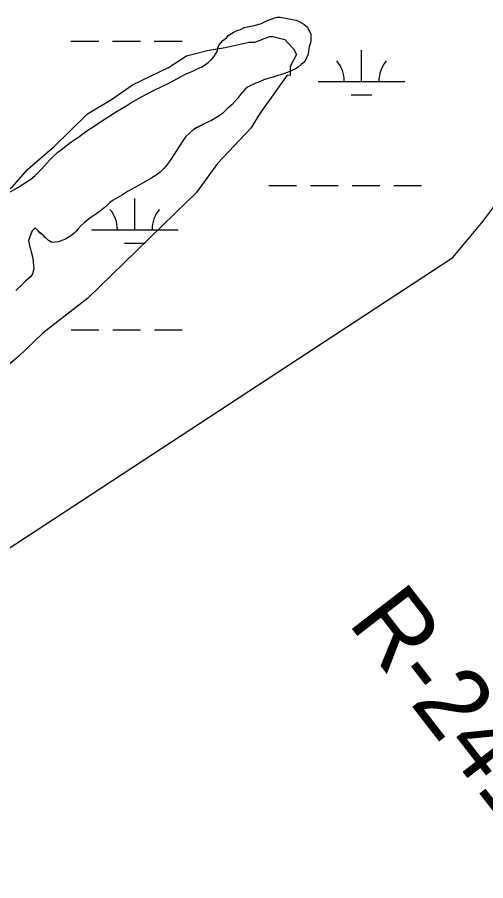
# Model space of a CAD drawing. Extents: x 3279314 to 3317160, y 734079 to 759431.
# Drawn here: x 3303115 to 3303655, y 741916 to 742911 of the extents above; entities that cross this region are included whole.
import ezdxf

# ---------------------------------------------------------------- set-up
doc = ezdxf.new("R2010")
doc.units = 0
for name, color, linetype in [('V-RIVR-RANG-IDEN', 7, 'Continuous'), ('V-SITE-VEGE', 7, 'Continuous'), ('V-TOPO-SHOR', 7, 'Continuous'), ('V-WETL-SWMP', 7, 'Continuous')]:
    doc.layers.add(name, color=color, linetype=linetype)

msp = doc.modelspace()

# ---------------------------------------------------------------- linework, layer by layer
at = {"layer": 'V-SITE-VEGE'}
msp.add_lwpolyline([(3303101.97, 742706.73), (3303116.96, 742715.21), (3303122.8, 742718.8), (3303130.92, 742724.2), (3303136, 742728.29), (3303142.84, 742735.21), (3303146.9, 742739.55), (3303152.47, 742745.95), (3303156.02, 742749.53), (3303162.11, 742755.16), (3303167.69, 742759.27), (3303175.56, 742765.67), (3303178.35, 742767.72), (3303187.74, 742773.88), (3303194.6, 742779.01), (3303205.26, 742785.94), (3303212.37, 742791.07), (3303230.4, 742802.61), (3303241.58, 742809.04), (3303245.13, 742811.35), (3303257.83, 742818.54), (3303273.84, 742827.02), (3303280.7, 742830.11), (3303290.87, 742835.25), (3303309.16, 742845.02), (3303312.97, 742846.82), (3303318.56, 742849.14), (3303322.12, 742850.94), (3303328.22, 742853.52), (3303332.54, 742856.34), (3303335.33, 742858.65), (3303339.39, 742862.23), (3303342.17, 742865.3), (3303345.71, 742871.43), (3303346.46, 742875.26), (3303347.97, 742878.83), (3303352.53, 742883.95), (3303356.59, 742887.02), (3303358.62, 742889.58), (3303362.17, 742892.14), (3303365.47, 742893.94), (3303368.78, 742895.49), (3303372.59, 742896.78), (3303376.91, 742898.84), (3303388.36, 742901.19), (3303397.01, 742903.52), (3303400.31, 742905.32), (3303403.87, 742906.86), (3303412.26, 742909.96), (3303415.32, 742910.74), (3303418.37, 742910.75), (3303426.53, 742909.52), (3303432.65, 742908.27), (3303436.47, 742907.27), (3303439.53, 742906.27), (3303443.11, 742904.5), (3303445.67, 742902.73), (3303450.01, 742899.19), (3303451.81, 742895.12), (3303453.62, 742891.56), (3303453.65, 742883.67), (3303453.16, 742880.1), (3303451.9, 742876.78), (3303450.91, 742871.94), (3303450.67, 742868.37), (3303448.15, 742862.24), (3303445.88, 742858.67), (3303443.08, 742856.62), (3303439.02, 742853.29), (3303436.23, 742851.49), (3303430.39, 742848.66), (3303426.57, 742847.11), (3303421.49, 742845.3), (3303413.35, 742842.97), (3303410.3, 742841.94), (3303404.19, 742840.13), (3303399.61, 742838.58), (3303393.77, 742836), (3303390.21, 742834.97), (3303380.81, 742830.34), (3303378.01, 742827.77), (3303372.69, 742821.89), (3303369.15, 742817.29), (3303363.07, 742810.13), (3303358.25, 742806.03), (3303351.91, 742799.89), (3303346.83, 742796.29), (3303339.22, 742791.68), (3303333.12, 742789.1), (3303321.68, 742783.18), (3303318.12, 742781.13), (3303309.75, 742773.45), (3303306.21, 742768.59), (3303291.55, 742745.6), (3303287.25, 742739.72), (3303284.46, 742736.65), (3303280.15, 742732.3), (3303276.85, 742729.73), (3303270.5, 742725.62), (3303255.01, 742716.89), (3303246.62, 742712.52), (3303242.31, 742709.96), (3303236.72, 742706.11), (3303225.79, 742700.19), (3303222.24, 742697.38), (3303217.17, 742692.51), (3303212.86, 742688.93), (3303205.75, 742683.55), (3303199.66, 742679.69), (3303192.55, 742674.06), (3303189.26, 742670.98), (3303185.71, 742666.89), (3303183.18, 742664.33), (3303180.64, 742661.52), (3303177.34, 742658.95), (3303170.23, 742654.84), (3303162.6, 742652.01), (3303159.04, 742651.73), (3303155.22, 742651.21), (3303151.64, 742653.74), (3303147.8, 742657.03), (3303145.5, 742659.82), (3303141.66, 742662.35), (3303139.36, 742664.63), (3303136.03, 742668.18), (3303132.74, 742664.6), (3303130.22, 742658.98), (3303128.46, 742653.63), (3303129.51, 742647.52), (3303130.8, 742643.7), (3303131.33, 742640.39), (3303133.4, 742633.28), (3303133.67, 742628.94), (3303134.48, 742620.8), (3303132.97, 742615.18), (3303130.95, 742612.12), (3303125.12, 742606.74), (3303120.81, 742602.39), (3303113.96, 742595.99)], dxfattribs=at)
at = {"layer": 'V-TOPO-SHOR'}
for points in [[(3303248.34, 742832.86), (3303289.7, 742852.78), (3303310.43, 742866.16), (3303334.48, 742872.64), (3303355.06, 742875.76), (3303382.54, 742882.19), (3303389.38, 742882.09), (3303406.59, 742888.67), (3303410.01, 742888.62), (3303423.64, 742885), (3303427.01, 742881.53), (3303433.75, 742874.58), (3303437.07, 742867.69), (3303430.02, 742854.1), (3303429.87, 742843.84), (3303426.45, 742843.89), (3303395, 742799.88)], [(3302509.04, 742364.81), (3302602.07, 742407.91), (3302664.17, 742441.2), (3302722.84, 742474.55), (3302798.88, 742524.74), (3302847.23, 742554.82), (3302895.59, 742584.9), (3302964.58, 742621.51), (3303009.46, 742648.22), (3303037.09, 742664.91), (3303075.18, 742695.14), (3303109.7, 742715.16), (3303127.12, 742735.43), (3303158.31, 742762.34), (3303175.68, 742779.2), (3303196.51, 742799.41), (3303224.14, 742816.11), (3303248.34, 742832.86)], [(3303395, 742799.88), (3303384.48, 742782.92), (3303346.23, 742742.43), (3303321.77, 742708.57), (3303297.46, 742684.98), (3303252.32, 742641.17), (3303224.54, 742614.21), (3303196.77, 742587.25), (3303144.83, 742546.95), (3303117.05, 742519.99), (3303068.54, 742479.65), (3303027.13, 742456.32), (3302971.88, 742422.92), (3302927.05, 742399.64), (3302847.79, 742363.18), (3302792.65, 742336.62), (3302706.5, 742296.84), (3302654.82, 742273.66), (3302603.1, 742247.06), (3302520.53, 742217.49)]]:
    msp.add_lwpolyline(points, dxfattribs=at)
at = {"layer": 'V-WETL-SWMP'}
for p, q in [((3303388.36, 742901.19), (3303397.01, 742903.52)), ((3303388.36, 742901.19), (3303397.01, 742903.52)), ((3303397.01, 742903.52), (3303400.31, 742905.32)), ((3303397.01, 742903.52), (3303400.31, 742905.32)), ((3303400.31, 742905.32), (3303403.87, 742906.86)), ((3303400.31, 742905.32), (3303403.87, 742906.86)), ((3303403.87, 742906.86), (3303412.26, 742909.96)), ((3303403.87, 742906.86), (3303412.26, 742909.96)), ((3303412.26, 742909.96), (3303415.32, 742910.74)), ((3303412.26, 742909.96), (3303415.32, 742910.74)), ((3303415.32, 742910.74), (3303418.37, 742910.75)), ((3303415.32, 742910.74), (3303418.37, 742910.75)), ((3303418.37, 742910.75), (3303426.53, 742909.52)), ((3303418.37, 742910.75), (3303426.53, 742909.52)), ((3303426.53, 742909.52), (3303432.65, 742908.27)), ((3303426.53, 742909.52), (3303432.65, 742908.27)), ((3303432.65, 742908.27), (3303436.47, 742907.27)), ((3303432.65, 742908.27), (3303436.47, 742907.27)), ((3303436.47, 742907.27), (3303439.54, 742906.27)), ((3303436.47, 742907.27), (3303439.54, 742906.27)), ((3303439.54, 742906.27), (3303443.11, 742904.5)), ((3303439.54, 742906.27), (3303443.11, 742904.5)), ((3303443.11, 742904.5), (3303445.67, 742902.73)), ((3303443.11, 742904.5), (3303445.67, 742902.73)), ((3303445.67, 742902.73), (3303450.01, 742899.19)), ((3303445.67, 742902.73), (3303450.01, 742899.19)), ((3303362.17, 742892.15), (3303365.47, 742893.94)), ((3303362.17, 742892.15), (3303365.47, 742893.94)), ((3303365.47, 742893.94), (3303368.78, 742895.49)), ((3303365.47, 742893.94), (3303368.78, 742895.49)), ((3303368.78, 742895.49), (3303372.59, 742896.78)), ((3303368.78, 742895.49), (3303372.59, 742896.78)), ((3303372.59, 742896.78), (3303376.91, 742898.84)), ((3303372.59, 742896.78), (3303376.91, 742898.84)), ((3303376.91, 742898.84), (3303388.36, 742901.19)), ((3303376.91, 742898.84), (3303388.36, 742901.19)), ((3303450.01, 742899.19), (3303451.82, 742895.12)), ((3303450.01, 742899.19), (3303451.82, 742895.12)), ((3303451.82, 742895.12), (3303453.62, 742891.56)), ((3303451.82, 742895.12), (3303453.62, 742891.56)), ((3303177.36, 742883.18), (3303209.36, 742883.19)), ((3303225.36, 742883.2), (3303257.36, 742883.22)), ((3303273.36, 742883.23), (3303305.36, 742883.24)), ((3303347.97, 742878.83), (3303352.53, 742883.95)), ((3303347.97, 742878.83), (3303352.53, 742883.95)), ((3303352.53, 742883.95), (3303356.59, 742887.02)), ((3303352.53, 742883.95), (3303356.59, 742887.02)), ((3303356.59, 742887.02), (3303358.62, 742889.58)), ((3303356.59, 742887.02), (3303358.62, 742889.58)), ((3303358.62, 742889.58), (3303362.17, 742892.15)), ((3303358.62, 742889.58), (3303362.17, 742892.15)), ((3303453.65, 742883.67), (3303453.16, 742880.1)), ((3303453.65, 742883.67), (3303453.16, 742880.1)), ((3303453.62, 742891.56), (3303453.65, 742883.67)), ((3303453.62, 742891.56), (3303453.65, 742883.67)), ((3303345.71, 742871.43), (3303346.46, 742875.26)), ((3303345.71, 742871.43), (3303346.46, 742875.26)), ((3303346.46, 742875.26), (3303347.97, 742878.83)), ((3303346.46, 742875.26), (3303347.97, 742878.83)), ((3303451.9, 742876.78), (3303450.91, 742871.94)), ((3303451.9, 742876.78), (3303450.91, 742871.94)), ((3303453.16, 742880.1), (3303451.9, 742876.78)), ((3303453.16, 742880.1), (3303451.9, 742876.78)), ((3303512.22, 742836.92), (3303512.21, 742872.92)), ((3303339.39, 742862.23), (3303342.18, 742865.3)), ((3303339.39, 742862.23), (3303342.18, 742865.3)), ((3303342.18, 742865.3), (3303345.71, 742871.43)), ((3303342.18, 742865.3), (3303345.71, 742871.43)), ((3303450.67, 742868.37), (3303448.15, 742862.25)), ((3303450.67, 742868.37), (3303448.15, 742862.25)), ((3303450.91, 742871.94), (3303450.67, 742868.37)), ((3303450.91, 742871.94), (3303450.67, 742868.37)), ((3303322.12, 742850.94), (3303328.22, 742853.52)), ((3303322.12, 742850.94), (3303328.22, 742853.52)), ((3303328.22, 742853.52), (3303332.54, 742856.34)), ((3303328.22, 742853.52), (3303332.54, 742856.34)), ((3303332.54, 742856.34), (3303335.33, 742858.65)), ((3303332.54, 742856.34), (3303335.33, 742858.65)), ((3303335.33, 742858.65), (3303339.39, 742862.23)), ((3303335.33, 742858.65), (3303339.39, 742862.23)), ((3303439.03, 742853.29), (3303436.23, 742851.49)), ((3303439.03, 742853.29), (3303436.23, 742851.49)), ((3303443.09, 742856.62), (3303439.03, 742853.29)), ((3303443.09, 742856.62), (3303439.03, 742853.29)), ((3303445.88, 742858.67), (3303443.09, 742856.62)), ((3303445.88, 742858.67), (3303443.09, 742856.62)), ((3303448.15, 742862.25), (3303445.88, 742858.67)), ((3303448.15, 742862.25), (3303445.88, 742858.67)), ((3303290.87, 742835.26), (3303309.16, 742845.02)), ((3303290.87, 742835.26), (3303309.16, 742845.02)), ((3303309.16, 742845.02), (3303312.97, 742846.82)), ((3303309.16, 742845.02), (3303312.97, 742846.82)), ((3303312.97, 742846.82), (3303318.56, 742849.14)), ((3303312.97, 742846.82), (3303318.56, 742849.14)), ((3303318.56, 742849.14), (3303322.12, 742850.94)), ((3303318.56, 742849.14), (3303322.12, 742850.94)), ((3303413.35, 742842.98), (3303410.3, 742841.94)), ((3303413.35, 742842.98), (3303410.3, 742841.94)), ((3303421.49, 742845.31), (3303413.35, 742842.98)), ((3303421.49, 742845.31), (3303413.35, 742842.98)), ((3303426.58, 742847.11), (3303421.49, 742845.31)), ((3303426.58, 742847.11), (3303421.49, 742845.31)), ((3303430.39, 742848.66), (3303426.58, 742847.11)), ((3303430.39, 742848.66), (3303426.58, 742847.11)), ((3303436.23, 742851.49), (3303430.39, 742848.66)), ((3303436.23, 742851.49), (3303430.39, 742848.66)), ((3303280.7, 742830.11), (3303290.87, 742835.26)), ((3303280.7, 742830.11), (3303290.87, 742835.26)), ((3303390.21, 742834.97), (3303380.81, 742830.34)), ((3303390.21, 742834.97), (3303380.81, 742830.34)), ((3303393.77, 742836), (3303390.21, 742834.97)), ((3303393.77, 742836), (3303390.21, 742834.97)), ((3303399.62, 742838.58), (3303393.77, 742836)), ((3303399.62, 742838.58), (3303393.77, 742836)), ((3303404.19, 742840.13), (3303399.62, 742838.58)), ((3303404.19, 742840.13), (3303399.62, 742838.58)), ((3303410.3, 742841.94), (3303404.19, 742840.13)), ((3303410.3, 742841.94), (3303404.19, 742840.13)), ((3303462.22, 742836.89), (3303562.22, 742836.94)), ((3303257.83, 742818.54), (3303273.84, 742827.02)), ((3303257.83, 742818.54), (3303273.84, 742827.02)), ((3303273.84, 742827.02), (3303280.7, 742830.11)), ((3303273.84, 742827.02), (3303280.7, 742830.11)), ((3303378.02, 742827.78), (3303372.7, 742821.89)), ((3303378.02, 742827.78), (3303372.7, 742821.89)), ((3303380.81, 742830.34), (3303378.02, 742827.78)), ((3303380.81, 742830.34), (3303378.02, 742827.78)), ((3303245.13, 742811.35), (3303257.83, 742818.54)), ((3303245.13, 742811.35), (3303257.83, 742818.54)), ((3303369.15, 742817.29), (3303363.07, 742810.13)), ((3303369.15, 742817.29), (3303363.07, 742810.13)), ((3303372.7, 742821.89), (3303369.15, 742817.29)), ((3303372.7, 742821.89), (3303369.15, 742817.29)), ((3303500.23, 742821.48), (3303524.23, 742821.49)), ((3303230.4, 742802.62), (3303241.58, 742809.04)), ((3303230.4, 742802.62), (3303241.58, 742809.04)), ((3303241.58, 742809.04), (3303245.13, 742811.35)), ((3303241.58, 742809.04), (3303245.13, 742811.35)), ((3303358.25, 742806.03), (3303351.91, 742799.89)), ((3303358.25, 742806.03), (3303351.91, 742799.89)), ((3303363.07, 742810.13), (3303358.25, 742806.03)), ((3303363.07, 742810.13), (3303358.25, 742806.03)), ((3303212.37, 742791.07), (3303230.4, 742802.62)), ((3303212.37, 742791.07), (3303230.4, 742802.62)), ((3303346.84, 742796.3), (3303339.22, 742791.68)), ((3303346.84, 742796.3), (3303339.22, 742791.68)), ((3303351.91, 742799.89), (3303346.84, 742796.3)), ((3303351.91, 742799.89), (3303346.84, 742796.3)), ((3303194.6, 742779.01), (3303205.26, 742785.94)), ((3303194.6, 742779.01), (3303205.26, 742785.94)), ((3303205.26, 742785.94), (3303212.37, 742791.07)), ((3303205.26, 742785.94), (3303212.37, 742791.07)), ((3303321.68, 742783.19), (3303318.13, 742781.13)), ((3303321.68, 742783.19), (3303318.13, 742781.13)), ((3303333.12, 742789.1), (3303321.68, 742783.19)), ((3303333.12, 742789.1), (3303321.68, 742783.19)), ((3303339.22, 742791.68), (3303333.12, 742789.1)), ((3303339.22, 742791.68), (3303333.12, 742789.1)), ((3303178.35, 742767.73), (3303187.75, 742773.88)), ((3303178.35, 742767.73), (3303187.75, 742773.88)), ((3303187.75, 742773.88), (3303194.6, 742779.01)), ((3303187.75, 742773.88), (3303194.6, 742779.01)), ((3303309.76, 742773.45), (3303306.21, 742768.59)), ((3303309.76, 742773.45), (3303306.21, 742768.59)), ((3303318.13, 742781.13), (3303309.76, 742773.45)), ((3303318.13, 742781.13), (3303309.76, 742773.45)), ((3303167.69, 742759.27), (3303175.56, 742765.67)), ((3303167.69, 742759.27), (3303175.56, 742765.67)), ((3303175.56, 742765.67), (3303178.35, 742767.73)), ((3303175.56, 742765.67), (3303178.35, 742767.73)), ((3303306.21, 742768.59), (3303291.55, 742745.6)), ((3303306.21, 742768.59), (3303291.55, 742745.6)), ((3303156.02, 742749.53), (3303162.11, 742755.17)), ((3303156.02, 742749.53), (3303162.11, 742755.17)), ((3303162.11, 742755.17), (3303167.69, 742759.27)), ((3303162.11, 742755.17), (3303167.69, 742759.27)), ((3303146.9, 742739.56), (3303152.47, 742745.95)), ((3303146.9, 742739.56), (3303152.47, 742745.95)), ((3303152.47, 742745.95), (3303156.02, 742749.53)), ((3303152.47, 742745.95), (3303156.02, 742749.53)), ((3303291.55, 742745.6), (3303287.25, 742739.72)), ((3303291.55, 742745.6), (3303287.25, 742739.72)), ((3303136, 742728.3), (3303142.85, 742735.21)), ((3303136, 742728.3), (3303142.85, 742735.21)), ((3303142.85, 742735.21), (3303146.9, 742739.56)), ((3303142.85, 742735.21), (3303146.9, 742739.56)), ((3303284.46, 742736.65), (3303280.15, 742732.3)), ((3303284.46, 742736.65), (3303280.15, 742732.3)), ((3303287.25, 742739.72), (3303284.46, 742736.65)), ((3303287.25, 742739.72), (3303284.46, 742736.65)), ((3303122.8, 742718.81), (3303130.93, 742724.2)), ((3303122.8, 742718.81), (3303130.93, 742724.2)), ((3303130.93, 742724.2), (3303136, 742728.3)), ((3303130.93, 742724.2), (3303136, 742728.3)), ((3303270.51, 742725.63), (3303255.01, 742716.89)), ((3303270.51, 742725.63), (3303255.01, 742716.89)), ((3303276.85, 742729.74), (3303270.51, 742725.63)), ((3303276.85, 742729.74), (3303270.51, 742725.63)), ((3303280.15, 742732.3), (3303276.85, 742729.74)), ((3303280.15, 742732.3), (3303276.85, 742729.74)), ((3303101.97, 742706.74), (3303116.96, 742715.21)), ((3303101.97, 742706.74), (3303116.96, 742715.21)), ((3303116.96, 742715.21), (3303122.8, 742718.81)), ((3303116.96, 742715.21), (3303122.8, 742718.81)), ((3303255.01, 742716.89), (3303246.62, 742712.52)), ((3303255.01, 742716.89), (3303246.62, 742712.52)), ((3303405.44, 742716.79), (3303437.44, 742716.81)), ((3303453.44, 742716.82), (3303485.44, 742716.83)), ((3303501.44, 742716.84), (3303533.44, 742716.86)), ((3303549.44, 742716.87), (3303581.44, 742716.88)), ((3303652.03, 742675.5), (3303685.92, 742720.88)), ((3303652.03, 742675.5), (3303685.92, 742720.88)), ((3303236.72, 742706.11), (3303225.8, 742700.2)), ((3303236.72, 742706.11), (3303225.8, 742700.2)), ((3303242.31, 742709.96), (3303236.72, 742706.11)), ((3303242.31, 742709.96), (3303236.72, 742706.11)), ((3303246.62, 742712.52), (3303242.31, 742709.96)), ((3303246.62, 742712.52), (3303242.31, 742709.96)), ((3303222.24, 742697.38), (3303217.17, 742692.51)), ((3303222.24, 742697.38), (3303217.17, 742692.51)), ((3303225.8, 742700.2), (3303222.24, 742697.38)), ((3303225.8, 742700.2), (3303222.24, 742697.38)), ((3303250.88, 742665.97), (3303250.86, 742701.97)), ((3303212.86, 742688.93), (3303205.75, 742683.55)), ((3303212.86, 742688.93), (3303205.75, 742683.55)), ((3303217.17, 742692.51), (3303212.86, 742688.93)), ((3303217.17, 742692.51), (3303212.86, 742688.93)), ((3303192.55, 742674.06), (3303189.26, 742670.98)), ((3303192.55, 742674.06), (3303189.26, 742670.98)), ((3303199.66, 742679.7), (3303192.55, 742674.06)), ((3303199.66, 742679.7), (3303192.55, 742674.06)), ((3303205.75, 742683.55), (3303199.66, 742679.7)), ((3303205.75, 742683.55), (3303199.66, 742679.7)), ((3303617.32, 742634.09), (3303652.03, 742675.5)), ((3303617.32, 742634.09), (3303652.03, 742675.5)), ((3303132.74, 742664.6), (3303130.22, 742658.98)), ((3303132.74, 742664.6), (3303130.22, 742658.98)), ((3303136.04, 742668.18), (3303132.74, 742664.6)), ((3303136.04, 742668.18), (3303132.74, 742664.6)), ((3303139.36, 742664.63), (3303136.04, 742668.18)), ((3303139.36, 742664.63), (3303136.04, 742668.18)), ((3303141.67, 742662.35), (3303139.36, 742664.63)), ((3303141.67, 742662.35), (3303139.36, 742664.63)), ((3303183.18, 742664.33), (3303180.64, 742661.52)), ((3303183.18, 742664.33), (3303180.64, 742661.52)), ((3303185.71, 742666.89), (3303183.18, 742664.33)), ((3303185.71, 742666.89), (3303183.18, 742664.33)), ((3303189.26, 742670.98), (3303185.71, 742666.89)), ((3303189.26, 742670.98), (3303185.71, 742666.89)), ((3303200.88, 742665.95), (3303300.88, 742666)), ((3303130.22, 742658.98), (3303128.46, 742653.63)), ((3303130.22, 742658.98), (3303128.46, 742653.63)), ((3303145.5, 742659.82), (3303141.67, 742662.35)), ((3303145.5, 742659.82), (3303141.67, 742662.35)), ((3303147.81, 742657.03), (3303145.5, 742659.82)), ((3303147.81, 742657.03), (3303145.5, 742659.82)), ((3303151.64, 742653.74), (3303147.81, 742657.03)), ((3303151.64, 742653.74), (3303147.81, 742657.03)), ((3303170.23, 742654.85), (3303162.6, 742652.01)), ((3303170.23, 742654.85), (3303162.6, 742652.01)), ((3303177.34, 742658.96), (3303170.23, 742654.85)), ((3303177.34, 742658.96), (3303170.23, 742654.85)), ((3303180.64, 742661.52), (3303177.34, 742658.96)), ((3303180.64, 742661.52), (3303177.34, 742658.96)), ((3303128.46, 742653.63), (3303129.51, 742647.52)), ((3303128.46, 742653.63), (3303129.51, 742647.52)), ((3303129.51, 742647.52), (3303130.8, 742643.7)), ((3303129.51, 742647.52), (3303130.8, 742643.7)), ((3303155.22, 742651.21), (3303151.64, 742653.74)), ((3303155.22, 742651.21), (3303151.64, 742653.74)), ((3303159.04, 742651.74), (3303155.22, 742651.21)), ((3303159.04, 742651.74), (3303155.22, 742651.21)), ((3303162.6, 742652.01), (3303159.04, 742651.74)), ((3303162.6, 742652.01), (3303159.04, 742651.74)), ((3303238.88, 742650.53), (3303262.88, 742650.55)), ((3303102.54, 742296.87), (3303617.32, 742634.09)), ((3303102.54, 742296.87), (3303617.32, 742634.09)), ((3303130.8, 742643.7), (3303131.33, 742640.4)), ((3303130.8, 742643.7), (3303131.33, 742640.4)), ((3303131.33, 742640.4), (3303133.4, 742633.27)), ((3303131.33, 742640.4), (3303133.4, 742633.27)), ((3303133.4, 742633.27), (3303133.68, 742628.94)), ((3303133.4, 742633.27), (3303133.68, 742628.94)), ((3303133.68, 742628.94), (3303134.48, 742620.8)), ((3303133.68, 742628.94), (3303134.48, 742620.8)), ((3303132.98, 742615.19), (3303130.96, 742612.12)), ((3303132.98, 742615.19), (3303130.96, 742612.12)), ((3303134.48, 742620.8), (3303132.98, 742615.19)), ((3303134.48, 742620.8), (3303132.98, 742615.19)), ((3303125.12, 742606.74), (3303120.81, 742602.39)), ((3303125.12, 742606.74), (3303120.81, 742602.39)), ((3303130.96, 742612.12), (3303125.12, 742606.74)), ((3303130.96, 742612.12), (3303125.12, 742606.74)), ((3303120.81, 742602.39), (3303113.97, 742595.99)), ((3303120.81, 742602.39), (3303113.97, 742595.99)), ((3303177.53, 742550.5), (3303209.53, 742550.52)), ((3303225.53, 742550.53), (3303257.53, 742550.54)), ((3303273.53, 742550.55), (3303305.53, 742550.57))]:
    msp.add_line(p, q, dxfattribs=at)
for centre, start, end in [((3303456.98, 742837.36), 359.25735, 40.801), ((3303567.47, 742837.42), 139.25734, 180.801), ((3303195.63, 742666.42), 359.25735, 40.801), ((3303306.12, 742666.47), 139.25734, 180.801)]:
    msp.add_arc(centre, 35.25, start, end, dxfattribs=at)

# ---------------------------------------------------------------- texts
at = {"layer": 'V-RIVR-RANG-IDEN'}
msp.add_text('R-241.9', height=83, rotation=307.77447, dxfattribs=at).set_placement((3303495.45, 742213.35))

doc.saveas('drawing.dxf')
